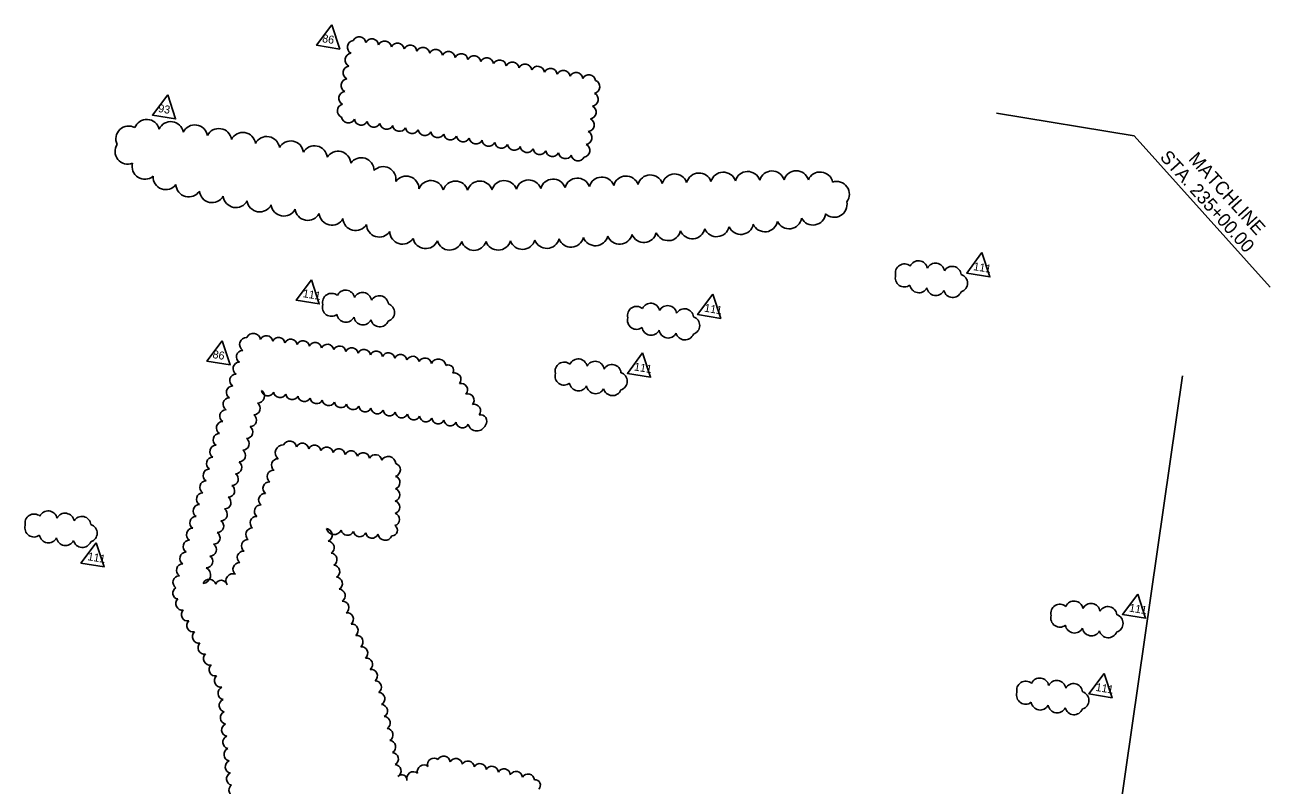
# Model space of a CAD drawing. Extents: x 927483 to 928746, y 636242 to 637203.
# Drawn here: x 927999 to 928746, y 636688 to 637144 of the extents above; entities that cross this region are included whole.
import ezdxf

# ---------------------------------------------------------------- set-up
doc = ezdxf.new("R2010")
doc.units = 0
doc.layers.add('Cloud_dp', color=7, linetype='Continuous')
doc.layers.add('MatchLines_dp', color=7, linetype='Continuous')

msp = doc.modelspace()

# ---------------------------------------------------------------- linework, layer by layer
at = {"layer": 'Cloud_dp'}
for points in [[(928182.7, 637144.2), (928173.55, 637131.97), (928187.45, 637129.68)], [(928084.3, 637102.26), (928075.15, 637090.02), (928089.05, 637087.73)], [(928572.74, 637007.49), (928563.59, 636995.25), (928577.49, 636992.96)], [(928170.49, 636991.25), (928161.34, 636979.01), (928175.23, 636976.72)], [(928411.3, 636982.56), (928402.15, 636970.32), (928416.04, 636968.03)], [(928116.97, 636954.6), (928107.81, 636942.36), (928121.71, 636940.07)], [(928369.2, 636947.28), (928360.04, 636935.05), (928373.94, 636932.75)], [(928041.37, 636833.37), (928032.22, 636821.14), (928046.12, 636818.85)], [(928666.19, 636802.56), (928657.04, 636790.32), (928670.93, 636788.03)], [(928646.1, 636754.9), (928636.94, 636742.66), (928650.84, 636740.37)]]:
    msp.add_lwpolyline(points, close=True, dxfattribs=at)
for centre, radius, start, end in [((928196.08, 637130.79), 4.07, 98.13813, 243.13813), ((928199.13, 637132.98), 4.07, 8.13813, 153.13813), ((928206.78, 637131.72), 4.07, 8.13813, 153.13813), ((928214.44, 637130.46), 4.07, 8.13813, 153.13813), ((928222.09, 637129.2), 4.07, 8.13813, 153.13813), ((928229.75, 637127.93), 4.07, 8.13813, 153.13813), ((928237.41, 637126.67), 4.07, 8.13813, 153.13813), ((928245.06, 637125.41), 4.07, 8.13813, 153.13813), ((928252.72, 637124.15), 4.07, 8.13813, 153.13813), ((928194.81, 637123.14), 4.07, 98.13813, 243.13813), ((928260.37, 637122.89), 4.07, 8.13813, 153.13813), ((928268.03, 637121.62), 4.07, 8.13813, 153.13813), ((928275.68, 637120.36), 4.07, 8.13813, 153.13813), ((928283.34, 637119.1), 4.07, 8.13813, 153.13813), ((928290.99, 637117.84), 4.07, 8.13813, 153.13813), ((928298.65, 637116.58), 4.07, 8.13813, 153.13813), ((928193.55, 637115.48), 4.07, 98.13813, 243.13813), ((928306.3, 637115.31), 4.07, 8.13813, 153.13813), ((928313.96, 637114.05), 4.07, 8.13813, 153.13813), ((928321.61, 637112.79), 4.07, 8.13813, 153.13813), ((928329.27, 637111.53), 4.07, 8.13813, 153.13813), ((928336.92, 637110.27), 4.07, 8.13813, 153.13813), ((928192.29, 637107.83), 4.07, 98.13813, 243.13813), ((928339.45, 637107.06), 4.06, 283.30989, 68.30989), ((928191.03, 637100.17), 4.07, 98.13813, 243.13813), ((928338.55, 637099.48), 4.07, 278.13813, 63.13813), ((928190.13, 637092.59), 4.06, 103.30989, 248.30989), ((928337.28, 637091.83), 4.07, 278.13813, 63.13813), ((928060.84, 637075.84), 7.65, 60.84977, 205.84977), ((928071.73, 637079.81), 7.66, 14.24344, 159.24344), ((928086.11, 637078.49), 7.66, 10.32801, 155.32801), ((928100.54, 637076.53), 7.66, 9.19049, 154.19049), ((928192.65, 637089.39), 4.07, 188.13813, 333.13813), ((928200.31, 637088.13), 4.07, 188.13813, 333.13813), ((928207.96, 637086.87), 4.07, 188.13813, 333.13813), ((928215.62, 637085.6), 4.07, 188.13813, 333.13813), ((928223.27, 637084.34), 4.07, 188.13813, 333.13813), ((928230.93, 637083.08), 4.07, 188.13813, 333.13813), ((928336.02, 637084.17), 4.07, 278.13813, 63.13813), ((928114.96, 637074.34), 7.66, 8.5586, 153.5586), ((928129.37, 637072.02), 7.66, 8.10522, 153.10522), ((928143.74, 637069.56), 7.66, 7.4572, 152.4572), ((928238.58, 637081.82), 4.07, 188.13813, 333.13813), ((928246.24, 637080.55), 4.07, 188.13813, 333.13813), ((928253.89, 637079.29), 4.07, 188.13813, 333.13813), ((928261.55, 637078.03), 4.07, 188.13813, 333.13813), ((928269.2, 637076.77), 4.07, 188.13813, 333.13813), ((928276.86, 637075.51), 4.07, 188.13813, 333.13813), ((928334.76, 637076.52), 4.07, 278.13813, 63.13813), ((928060.35, 637068.28), 7.66, 146.56649, 291.56649), ((928158.07, 637066.91), 7.66, 6.57859, 151.57859), ((928172.33, 637064), 7.66, 5.36469, 150.36469), ((928186.49, 637060.72), 7.66, 3.52912, 148.52912), ((928284.51, 637074.24), 4.07, 188.13813, 333.13813), ((928292.17, 637072.98), 4.07, 188.13813, 333.13813), ((928299.82, 637071.72), 4.07, 188.13813, 333.13813), ((928307.48, 637070.46), 4.07, 188.13813, 333.13813), ((928315.13, 637069.2), 4.07, 188.13813, 333.13813), ((928333.5, 637068.86), 4.07, 278.13813, 63.13813), ((928070.56, 637059.18), 7.66, 165.01809, 310.01809), ((928200.42, 637056.81), 7.66, 0.16647, 145.16647), ((928322.79, 637067.93), 4.07, 188.13813, 333.13813), ((928330.44, 637066.67), 4.07, 188.13813, 333.13813), ((928083.14, 637052.97), 7.66, 177.47519, 322.47519), ((928213.57, 637051.49), 7.66, 350.76518, 135.76518), ((928227.36, 637045.81), 7.66, 359.43065, 144.43065), ((928344.63, 637045.17), 7.66, 20.05135, 165.05135), ((928359.22, 637045.83), 7.66, 20.09422, 165.09422), ((928373.81, 637046.48), 7.66, 19.96526, 164.96526), ((928388.4, 637047.08), 7.66, 19.80738, 164.80738), ((928402.99, 637047.65), 7.66, 19.60805, 164.60805), ((928417.58, 637048.15), 7.66, 19.34518, 164.34518), ((928432.17, 637048.57), 7.66, 18.97553, 163.97553), ((928446.75, 637048.87), 7.66, 18.39837, 163.39837), ((928461.31, 637048.96), 7.66, 17.28971, 162.28971), ((928475.68, 637048.25), 7.66, 12.07307, 157.07307), ((928096.87, 637048.63), 7.66, 182.36643, 327.36643), ((928242.22, 637043.13), 7.66, 15.15085, 160.15085), ((928256.9, 637042.79), 7.66, 17.20143, 162.20143), ((928271.55, 637042.84), 7.66, 18.201, 163.201), ((928286.18, 637043.1), 7.66, 18.82335, 163.82335), ((928300.8, 637043.5), 7.66, 19.25885, 164.25885), ((928315.42, 637043.99), 7.66, 19.58561, 164.58561), ((928330.02, 637044.55), 7.66, 19.8425, 164.8425), ((928485.55, 637042.58), 7.66, 323.09657, 108.09657), ((928110.95, 637045.16), 7.66, 184.97784, 329.97784), ((928125.19, 637042.22), 7.66, 186.65959, 331.65959), ((928139.51, 637039.62), 7.66, 187.81698, 332.81698), ((928484.18, 637036.39), 7.66, 227.01012, 12.01012), ((928153.92, 637037.14), 7.66, 187.65548, 332.65548), ((928168.33, 637034.53), 7.66, 186.81786, 331.81786), ((928182.7, 637031.67), 7.66, 185.63907, 330.63907), ((928471.35, 637031.75), 7.66, 207.77587, 352.77587), ((928197.01, 637028.42), 7.66, 183.7993, 328.7993), ((928211.22, 637024.49), 7.66, 180.29089, 325.29089), ((928413.57, 637024.73), 7.66, 202.63584, 347.63584), ((928428.09, 637026.11), 7.66, 203.20278, 348.20278), ((928442.58, 637027.66), 7.66, 204.00585, 349.00585), ((928457.03, 637029.47), 7.66, 205.275, 350.275), ((928225.18, 637020.23), 7.66, 180.71746, 325.71746), ((928238.99, 637017.55), 7.66, 192.29896, 337.29896), ((928311.66, 637017.72), 7.66, 200.16812, 345.16812), ((928326.23, 637018.46), 7.66, 200.63235, 345.63235), ((928340.8, 637019.31), 7.66, 201.00994, 346.00994), ((928355.36, 637020.24), 7.66, 201.32485, 346.32485), ((928369.93, 637021.25), 7.66, 201.59414, 346.59414), ((928384.48, 637022.33), 7.66, 201.87048, 346.87048), ((928399.03, 637023.48), 7.66, 202.20808, 347.20808), ((928253.42, 637016.69), 7.66, 195.88813, 340.88813), ((928267.95, 637016.51), 7.66, 197.67395, 342.67395), ((928282.52, 637016.69), 7.66, 198.79291, 343.79291), ((928297.09, 637017.12), 7.66, 199.57811, 344.57811), ((928526.23, 636995.29), 5.42, 49.77309, 194.77309), ((928534.68, 636997.2), 5.42, 10.81232, 155.81232), ((928544.85, 636995.78), 5.42, 8.20535, 153.20535), ((928526.17, 636992.33), 5.42, 163.13084, 308.13084), ((928554.92, 636993.86), 5.42, 5.2898, 150.2898), ((928558.66, 636989.21), 5.42, 287.14219, 72.14219), ((928534.89, 636988.83), 5.42, 188.13813, 333.13813), ((928545.1, 636987.16), 5.42, 188.21634, 333.21634), ((928182.54, 636977.67), 5.42, 49.77309, 194.77309), ((928190.99, 636979.58), 5.42, 10.81232, 155.81232), ((928201.16, 636978.16), 5.42, 8.20535, 153.20535), ((928211.24, 636976.24), 5.42, 5.2898, 150.2898), ((928555.21, 636986), 5.42, 193.70912, 338.70912), ((928182.49, 636974.71), 5.42, 163.13084, 308.13084), ((928191.21, 636971.21), 5.42, 188.13813, 333.13813), ((928214.98, 636971.59), 5.42, 287.14219, 72.14219), ((928365.6, 636969.82), 5.42, 49.77309, 194.77309), ((928374.05, 636971.73), 5.42, 10.81232, 155.81232), ((928384.22, 636970.31), 5.42, 8.20535, 153.20535), ((928394.29, 636968.39), 5.42, 5.2898, 150.2898), ((928201.41, 636969.54), 5.42, 188.21634, 333.21634), ((928211.52, 636968.38), 5.42, 193.70912, 338.70912), ((928365.54, 636966.86), 5.42, 163.13084, 308.13084), ((928398.03, 636963.74), 5.42, 287.14219, 72.14219), ((928131.73, 636952.34), 4.29, 89.69148, 234.69148), ((928135.68, 636954.75), 4.34, 9.48899, 154.48899), ((928143.46, 636953.8), 3.88, 9.48899, 154.48899), ((928150.78, 636952.77), 3.88, 9.48899, 154.48899), ((928158.1, 636951.74), 3.88, 9.48899, 154.48899), ((928374.26, 636963.36), 5.42, 188.13813, 333.13813), ((928384.47, 636961.69), 5.42, 188.21634, 333.21634), ((928394.58, 636960.53), 5.42, 193.70912, 338.70912), ((928129.38, 636944.97), 3.88, 91.81354, 236.81354), ((928165.42, 636950.71), 3.88, 9.48899, 154.48899), ((928172.74, 636949.68), 3.88, 9.48899, 154.48899), ((928180.06, 636948.65), 3.88, 9.48899, 154.48899), ((928187.38, 636947.62), 3.88, 9.48899, 154.48899), ((928194.7, 636946.59), 3.88, 9.48899, 154.48899), ((928202.02, 636945.56), 3.88, 9.48899, 154.48899), ((928209.35, 636944.53), 3.88, 9.48899, 154.48899), ((928127.38, 636937.85), 3.88, 91.81354, 236.81354), ((928216.67, 636943.5), 3.88, 9.48899, 154.48899), ((928223.99, 636942.46), 3.88, 9.48899, 154.48899), ((928231.31, 636941.43), 3.88, 9.48899, 154.48899), ((928238.63, 636940.4), 3.88, 9.48899, 154.48899), ((928246.68, 636939.02), 4.69, 9.48899, 154.48899), ((928322.1, 636936.39), 5.42, 49.77309, 194.77309), ((928330.55, 636938.3), 5.42, 10.81232, 155.81232), ((928340.72, 636936.88), 5.42, 8.20535, 153.20535), ((928125.38, 636930.73), 3.88, 91.81354, 236.81354), ((928252.61, 636936.85), 3.23, 328.96641, 113.96641), ((928256.35, 636931.43), 3.88, 319.48735, 104.48735), ((928322.05, 636933.43), 5.42, 163.13084, 308.13084), ((928350.8, 636934.96), 5.42, 5.2898, 150.2898), ((928354.53, 636930.31), 5.42, 287.14219, 72.14219), ((928123.38, 636923.61), 3.88, 91.81354, 236.81354), ((928260.27, 636925.16), 3.88, 319.48735, 104.48735), ((928330.76, 636929.93), 5.42, 188.13813, 333.13813), ((928340.97, 636928.26), 5.42, 188.21634, 333.21634), ((928351.08, 636927.1), 5.42, 193.70912, 338.70912), ((928121.38, 636916.49), 3.88, 91.81354, 236.81354), ((928138.1, 636921.38), 4.19, 270.24382, 55.24382), ((928144.33, 636925.47), 3.9, 189.62292, 334.62292), ((928151.7, 636924.34), 3.88, 188.0889, 333.0889), ((928158.99, 636923.13), 3.88, 188.0889, 333.0889), ((928166.29, 636921.92), 3.88, 188.0889, 333.0889), ((928173.58, 636920.71), 3.88, 188.0889, 333.0889), ((928180.87, 636919.5), 3.88, 188.0889, 333.0889), ((928264.18, 636918.89), 3.88, 319.48735, 104.48735), ((928119.38, 636909.38), 3.88, 91.81354, 236.81354), ((928135.91, 636914.01), 3.88, 270.24382, 55.24382), ((928188.17, 636918.3), 3.88, 188.0889, 333.0889), ((928195.46, 636917.09), 3.88, 188.0889, 333.0889), ((928202.75, 636915.88), 3.88, 188.0889, 333.0889), ((928210.05, 636914.67), 3.88, 188.0889, 333.0889), ((928217.34, 636913.46), 3.88, 188.0889, 333.0889), ((928224.64, 636912.25), 3.88, 188.0889, 333.0889), ((928268.1, 636912.62), 3.88, 319.48735, 104.48735), ((928117.38, 636902.26), 3.88, 91.81354, 236.81354), ((928133.71, 636906.95), 3.88, 270.24382, 55.24382), ((928231.93, 636911.04), 3.88, 188.0889, 333.0889), ((928239.22, 636909.83), 3.88, 188.0889, 333.0889), ((928246.52, 636908.62), 3.88, 188.0889, 333.0889), ((928253.81, 636907.41), 3.88, 188.0889, 333.0889), ((928261.1, 636906.21), 3.88, 188.0889, 333.0889), ((928269.76, 636905.86), 5.39, 195.17856, 340.17856), ((928271.98, 636906.47), 3.75, 319.48735, 104.48735), ((928115.39, 636895.14), 3.88, 91.81354, 236.81354), ((928129.33, 636892.83), 3.88, 270.24382, 55.24382), ((928131.52, 636899.89), 3.88, 270.24382, 55.24382), ((928113.39, 636888.02), 3.88, 91.81354, 236.81354), ((928127.14, 636885.77), 3.88, 270.24382, 55.24382), ((928153.5, 636887.5), 4.67, 86.91393, 231.91393), ((928157.47, 636890.32), 4.15, 8.65769, 153.65769), ((928165.05, 636889.23), 3.88, 8.65769, 153.65769), ((928172.35, 636888.09), 3.88, 8.65769, 153.65769), ((928179.66, 636886.95), 3.88, 8.65769, 153.65769), ((928186.96, 636885.82), 3.88, 8.65769, 153.65769), ((928194.27, 636884.68), 3.88, 8.65769, 153.65769), ((928111.39, 636880.91), 3.88, 91.81354, 236.81354), ((928124.94, 636878.7), 3.88, 270.24382, 55.24382), ((928150.42, 636879.96), 3.88, 87.16884, 232.16884), ((928201.57, 636883.54), 3.88, 8.65769, 153.65769), ((928208.88, 636882.41), 3.88, 8.65769, 153.65769), ((928216.56, 636880.67), 4.5, 3.94938, 148.94938), ((928219.78, 636877.11), 4.07, 286.81664, 71.81664), ((928109.39, 636873.79), 3.88, 91.81354, 236.81354), ((928122.75, 636871.64), 3.88, 270.24382, 55.24382), ((928147.86, 636873.03), 3.88, 87.16884, 232.16884), ((928107.39, 636866.67), 3.88, 91.81354, 236.81354), ((928120.56, 636864.58), 3.88, 270.24382, 55.24382), ((928145.29, 636866.09), 3.88, 87.16884, 232.16884), ((928219.66, 636862.14), 3.88, 286.81664, 71.81664), ((928219.75, 636869.53), 3.88, 286.81664, 71.81664), ((928105.39, 636859.55), 3.88, 91.81354, 236.81354), ((928118.36, 636857.52), 3.88, 270.24382, 55.24382), ((928142.72, 636859.16), 3.88, 87.16884, 232.16884), ((928219.57, 636854.74), 3.88, 286.81664, 71.81664), ((928012.54, 636847.11), 5.42, 10.81232, 155.81232), ((928022.7, 636845.69), 5.42, 8.20535, 153.20535), ((928103.39, 636852.44), 3.88, 91.81354, 236.81354), ((928116.17, 636850.46), 3.88, 270.24382, 55.24382), ((928140.15, 636852.23), 3.88, 87.16884, 232.16884), ((928219.49, 636847.35), 3.88, 286.81664, 71.81664), ((928004.03, 636842.24), 5.42, 163.13084, 308.13084), ((928004.09, 636845.2), 5.42, 49.77309, 194.77309), ((928032.78, 636843.77), 5.42, 5.2898, 150.2898), ((928036.52, 636839.12), 5.42, 287.14219, 72.14219), ((928101.39, 636845.32), 3.88, 91.81354, 236.81354), ((928113.98, 636843.4), 3.88, 270.24382, 55.24382), ((928137.58, 636845.3), 3.88, 87.16884, 232.16884), ((928218.72, 636840.84), 3.38, 271.05438, 56.05438), ((928012.75, 636838.74), 5.42, 188.13813, 333.13813), ((928022.96, 636837.07), 5.42, 188.21634, 333.21634), ((928099.39, 636838.2), 3.88, 91.81354, 236.81354), ((928111.78, 636836.34), 3.88, 270.24382, 55.24382), ((928135.01, 636838.36), 3.88, 87.16884, 232.16884), ((928184.15, 636842.87), 4.62, 190.8991, 335.8991), ((928178.91, 636838.02), 4.04, 294.91334, 79.91334), ((928192.17, 636841.72), 3.88, 190.8991, 335.8991), ((928199.52, 636840.87), 3.88, 190.8991, 335.8991), ((928206.86, 636840.02), 3.88, 190.8991, 335.8991), ((928214.74, 636839.27), 4.43, 190.8991, 335.8991), ((928033.07, 636835.91), 5.42, 193.70912, 338.70912), ((928097.4, 636831.08), 3.88, 91.81354, 236.81354), ((928109.59, 636829.28), 3.88, 270.24382, 55.24382), ((928132.44, 636831.43), 3.88, 87.16884, 232.16884), ((928180.3, 636830.49), 3.88, 300.37761, 85.37761), ((928095.4, 636823.96), 3.88, 91.81354, 236.81354), ((928107.4, 636822.22), 3.88, 270.24382, 55.24382), ((928127.31, 636817.57), 3.88, 87.16884, 232.16884), ((928129.88, 636824.5), 3.88, 87.16884, 232.16884), ((928181.95, 636823.28), 3.88, 300.37761, 85.37761), ((928091.4, 636809.63), 3.97, 91.81354, 236.81354), ((928093.4, 636816.85), 3.88, 91.81354, 236.81354), ((928105.02, 636813.94), 5.01, 276.48025, 61.48025), ((928123.43, 636810.51), 4.27, 69.46976, 214.46976), ((928183.59, 636816.08), 3.88, 300.37761, 85.37761), ((928090.82, 636803.13), 3.55, 116.61024, 261.61024), ((928109.26, 636807.56), 3.93, 14.04733, 159.04733), ((928116.43, 636807.23), 3.6, 14.04733, 159.04733), ((928185.24, 636808.87), 3.88, 300.37761, 85.37761), ((928093, 636796.84), 3.88, 134.23805, 279.23805), ((928186.89, 636801.67), 3.87, 300.37761, 85.37761), ((928096.33, 636790.24), 3.88, 134.23805, 279.23805), ((928189.03, 636794.47), 3.88, 307.80364, 92.80364), ((928191.78, 636787.54), 3.88, 310.4412, 95.4412), ((928619.55, 636791.07), 5.42, 49.77309, 194.77309), ((928628, 636792.99), 5.42, 10.81232, 155.81232), ((928638.17, 636791.56), 5.42, 8.20535, 153.20535), ((928648.25, 636789.65), 5.42, 5.2898, 150.2898), ((928099.66, 636783.64), 3.88, 134.23805, 279.23805), ((928194.66, 636780.74), 3.88, 310.4412, 95.4412), ((928619.5, 636788.12), 5.42, 163.13084, 308.13084), ((928628.22, 636784.62), 5.42, 188.13813, 333.13813), ((928651.99, 636784.99), 5.42, 287.14219, 72.14219), ((928102.98, 636777.03), 3.88, 134.23805, 279.23805), ((928197.54, 636773.93), 3.88, 310.4412, 95.4412), ((928638.42, 636782.95), 5.42, 188.21634, 333.21634), ((928648.53, 636781.79), 5.42, 193.70912, 338.70912), ((928106.31, 636770.43), 3.88, 134.23805, 279.23805), ((928200.42, 636767.12), 3.88, 310.4412, 95.4412), ((928109.64, 636763.83), 3.88, 134.23805, 279.23805), ((928203.31, 636760.31), 3.88, 310.4412, 95.4412), ((928112.96, 636757.23), 3.88, 134.23805, 279.23805), ((928206.19, 636753.5), 3.88, 310.4412, 95.4412), ((928116.26, 636750.52), 3.93, 132.79294, 277.79294), ((928118.31, 636743.06), 3.87, 113.11231, 258.11231), ((928208.73, 636746.72), 3.84, 305.40168, 90.40168), ((928599, 636744.85), 5.42, 49.77309, 194.77309), ((928607.45, 636746.76), 5.42, 10.81232, 155.81232), ((928617.62, 636745.34), 5.42, 8.20535, 153.20535), ((928627.7, 636743.42), 5.42, 5.2898, 150.2898), ((928119.03, 636735.71), 3.88, 113.11231, 258.11231), ((928210.63, 636739.69), 3.91, 300.25405, 85.25405), ((928598.95, 636741.89), 5.42, 163.13084, 308.13084), ((928631.44, 636738.77), 5.42, 287.14219, 72.14219), ((928119.75, 636728.35), 3.88, 113.11231, 258.11231), ((928212.28, 636732.45), 3.88, 300.25405, 85.25405), ((928607.67, 636738.39), 5.42, 188.13813, 333.13813), ((928617.87, 636736.72), 5.42, 188.21634, 333.21634), ((928627.98, 636735.56), 5.42, 193.70912, 338.70912), ((928120.48, 636721), 3.88, 113.11231, 258.11231), ((928213.91, 636725.24), 3.88, 300.25405, 85.25405), ((928121.2, 636713.64), 3.88, 113.11231, 258.11231), ((928215.54, 636718.03), 3.88, 300.25405, 85.25405), ((928121.92, 636706.28), 3.88, 113.11231, 258.11231), ((928217.17, 636710.82), 3.88, 300.25405, 85.25405), ((928122.65, 636698.92), 3.88, 113.11231, 258.11231), ((928218.8, 636703.61), 3.88, 300.25405, 85.25405), ((928244.02, 636700.25), 3.85, 51.34177, 196.34177), ((928249.87, 636701.44), 3.89, 7.28617, 152.28617), ((928257.09, 636700.02), 3.88, 5.37317, 150.37317), ((928264.32, 636698.47), 3.88, 5.37317, 150.37317), ((928123.34, 636691.63), 3.8, 113.11231, 258.11231), ((928220.44, 636696.4), 3.88, 300.25405, 85.25405), ((928224.74, 636691.06), 3.08, 354.65457, 139.65457), ((928231.67, 636691.9), 4.03, 51.34177, 196.34177), ((928237.91, 636696.14), 3.88, 51.34177, 196.34177), ((928271.55, 636696.92), 3.88, 5.37317, 150.37317), ((928278.78, 636695.36), 3.88, 5.37317, 150.37317), ((928286, 636693.81), 3.88, 5.37317, 150.37317), ((928293.23, 636692.26), 3.88, 5.37317, 150.37317), ((928300.46, 636690.7), 3.88, 5.37317, 150.37317), ((928125, 636684.79), 3.96, 128.01175, 273.01175), ((928304.71, 636687.92), 3.17, 312.00903, 97.00903)]:
    msp.add_arc(centre, radius, start, end, dxfattribs=at)
at = {"layer": 'MatchLines_dp'}
for p, q in [((928664.04, 637077.53), (928581.41, 637091.16)), ((928745.61, 636986.83), (928664.04, 637077.53)), ((928693.09, 636933.47), (928620.98, 636432.26))]:
    msp.add_line(p, q, dxfattribs=at)

# ---------------------------------------------------------------- texts
at = {"layer": 'Cloud_dp'}
for s, p in [('86', (928176.68, 637133.89)), ('93', (928078.28, 637091.95)), ('111', (928567.35, 636997.07)), ('111', (928165.09, 636980.83)), ('111', (928405.9, 636972.15)), ('86', (928110.95, 636944.29)), ('111', (928363.8, 636936.87)), ('111', (928035.98, 636822.96)), ('111', (928660.79, 636792.15)), ('111', (928640.7, 636744.49))]:
    msp.add_text(s, height=4.8, rotation=350.63813, dxfattribs=at).set_placement(p)
at = {"layer": 'MatchLines_dp'}
for s, p in [('STA. 235+00.00', (928679.06, 637064.5)), ('MATCHLINE', (928696.2, 637063.39))]:
    msp.add_text(s, height=8, rotation=311.9666, dxfattribs=at).set_placement(p)

doc.saveas('drawing.dxf')
